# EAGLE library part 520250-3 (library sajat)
AMP connector
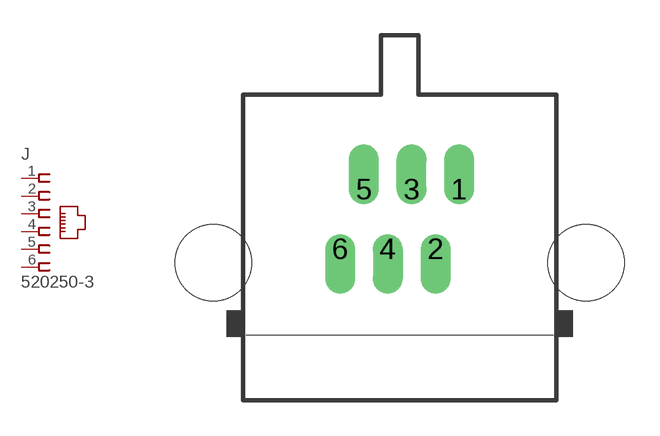
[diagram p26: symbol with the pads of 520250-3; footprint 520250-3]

Designator prefix J

## 520250-3  [520250-3]
1  1  pas
2  2  pas
3  3  pas
4  4  pas
5  5  pas
6  6  pas

## Footprint 520250-3 (pad centres in mm)
Modular Jack with Panel Stops
drill 0.6 pad 1.27 offset: 1 2.54,3.118; 2 1.524,0.578; 3 0.508,3.118; 4 -0.508,0.578; 5 -1.524,3.118; 6 -2.54,0.578
hole 3.251 at -7.938,0
hole 3.251 at 7.938,0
